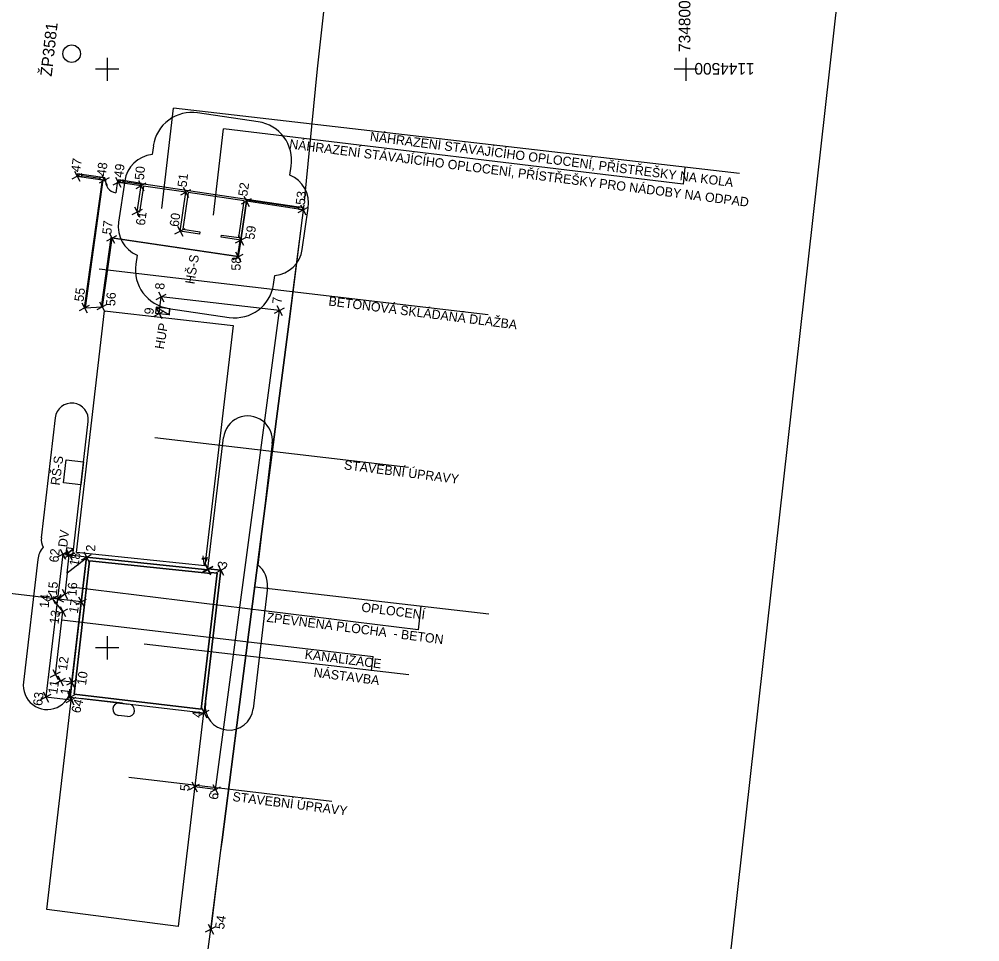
# Model space of a CAD drawing. Extents: x -734953 to -734775, y -1144697 to -1144368.
# Drawn here: x -734857.6 to -734774.6, y -1144575.4 to -1144495.7 of the extents above; entities that cross this region are included whole.
import ezdxf

# ---------------------------------------------------------------- set-up
doc = ezdxf.new("R2010")
doc.units = 0
for name, color, linetype in [('000_rozpiska', 7, 'Continuous'), ('A3_Netisk', 7, 'Continuous'), ('A3_SIT_OBJEKTY_N01', 7, 'Continuous'), ('A3_SIT_OBJEKTY_S01', 7, 'Continuous'), ('A3_SIT_PNB', 7, 'Continuous'), ('CKKOTY', 7, 'Continuous'), ('CKPLYN_POTRUBI_NT_PODZ_N', 7, 'Continuous'), ('CKTEXTY_MALE', 7, 'Continuous'), ('Katastr_HRANICE DRÁHY', 7, 'Continuous'), ('PROGI_rozpiska', 7, 'Continuous'), ('PROGI_vytyč_body', 7, 'Continuous'), ('PROGI_vytyč_čísla', 7, 'Continuous'), ('SO01_CKKANALIZACE_JEDNOTNA_PODZ_N', 7, 'Continuous'), ('čtvercová síť', 7, 'Continuous')]:
    doc.layers.add(name, color=color, linetype=linetype)

# ---------------------------------------------------------------- blocks, each defined once
blk = doc.blocks.new('POINT_DISPLAY')
for p, q in [((-0.35, -0.35), (0.35, 0.35)), ((-0.35, 0.35), (0.35, -0.35))]:
    blk.add_line(p, q)

msp = doc.modelspace()

# ---------------------------------------------------------------- linework, layer by layer
for p, q in [((-734795.363, -1144509.022), (-734844.273, -1144503.372)), ((-734817.078, -1144521.235), (-734850.682, -1144517.28)), ((-734823.968, -1144534.411), (-734845.892, -1144531.85)), ((-734853.579, -1144541.96), (-734852.914, -1144541.433)), ((-734817.019, -1144547.087), (-734837.249, -1144544.759)), ((-734823.952, -1144552.341), (-734846.794, -1144549.683)), ((-734830.58, -1144563.282), (-734848.143, -1144561.209))]:
    msp.add_line(p, q)
for points in [[(-734853.579, -1144541.96), (-734852.983, -1144542.029), (-734852.914, -1144541.433), (-734853.51, -1144541.364)], [(-734853.579, -1144541.96), (-734852.983, -1144542.029), (-734852.914, -1144541.433)]]:
    msp.add_lwpolyline(points, close=True)
at = {"layer": '000_rozpiska'}
msp.add_line((-734809.638, -1144697.109), (-734774.606, -1144384.063), dxfattribs=at)
at = {"layer": 'A3_Netisk'}
for p, q in [((-734800.085, -1144508.477), (-734800.248, -1144509.94)), ((-734838.465, -1144514.774), (-734837.936, -1144511.213)), ((-734851.783, -1144542.154), (-734853.2, -1144554.266)), ((-734848.694, -1144554.798), (-734852.306, -1144554.375))]:
    msp.add_line(p, q, dxfattribs=at)
msp.add_lwpolyline([(-734852.04, -1144533.939), (-734852.27, -1144535.925), (-734853.791, -1144535.749), (-734853.561, -1144533.763)], close=True, dxfattribs=at)
at = {"layer": 'A3_SIT_OBJEKTY_N01'}
for p, q in [((-734851.963, -1144520.613), (-734850.421, -1144509.56)), ((-734850.371, -1144509.567), (-734851.914, -1144520.619)), ((-734850.626, -1144509.529), (-734850.597, -1144509.332)), ((-734850.23, -1144509.588), (-734850.626, -1144509.529)), ((-734850.597, -1144509.332), (-734850.201, -1144509.39)), ((-734850.421, -1144509.56), (-734850.371, -1144509.567)), ((-734850.201, -1144509.39), (-734850.23, -1144509.588)), ((-734849.043, -1144509.765), (-734849.014, -1144509.567)), ((-734848.648, -1144509.823), (-734849.043, -1144509.765)), ((-734849.014, -1144509.567), (-734848.618, -1144509.626)), ((-734848.618, -1144509.626), (-734848.648, -1144509.823)), ((-734847.403, -1144512.334), (-734847.036, -1144509.861)), ((-734847.036, -1144509.861), (-734837.936, -1144511.213)), ((-734846.867, -1144510.088), (-734847.205, -1144512.363)), ((-734843.207, -1144510.632), (-734846.867, -1144510.088)), ((-734843.707, -1144513.995), (-734843.207, -1144510.632)), ((-734843.01, -1144510.661), (-734843.48, -1144513.826)), ((-734838.163, -1144511.381), (-734843.01, -1144510.661)), ((-734838.633, -1144514.546), (-734838.163, -1144511.381)), ((-734837.936, -1144511.213), (-734838.465, -1144514.774)), ((-734847.205, -1144512.363), (-734847.403, -1144512.334)), ((-734842.026, -1144514.245), (-734843.707, -1144513.995)), ((-734843.48, -1144513.826), (-734841.996, -1144514.047)), ((-734841.996, -1144514.047), (-734842.026, -1144514.245)), ((-734850.488, -1144520.532), (-734849.65, -1144514.527)), ((-734849.607, -1144514.584), (-734850.438, -1144520.538)), ((-734849.65, -1144514.527), (-734838.72, -1144516.151)), ((-734838.678, -1144516.208), (-734849.607, -1144514.584)), ((-734840.146, -1144514.524), (-734840.117, -1144514.326)), ((-734838.465, -1144514.774), (-734840.146, -1144514.524)), ((-734840.117, -1144514.326), (-734838.633, -1144514.546)), ((-734838.72, -1144516.151), (-734838.514, -1144514.766)), ((-734838.465, -1144514.774), (-734838.678, -1144516.208)), ((-734838.514, -1144514.766), (-734838.465, -1144514.774)), ((-734851.914, -1144520.619), (-734851.963, -1144520.613)), ((-734851.914, -1144520.619), (-734850.438, -1144520.538)), ((-734850.438, -1144520.538), (-734850.488, -1144520.532)), ((-734853.848, -1144541.911), (-734855.291, -1144554.247)), ((-734851.783, -1144542.154), (-734853.848, -1144541.911)), ((-734851.783, -1144542.154), (-734853.2, -1144554.27)), ((-734853.2, -1144554.27), (-734851.783, -1144542.154)), ((-734841.306, -1144543.249), (-734851.783, -1144542.154)), ((-734852.868, -1144554.007), (-734851.519, -1144542.484)), ((-734851.519, -1144542.484), (-734841.043, -1144543.578)), ((-734841.297, -1144543.168), (-734841.306, -1144543.249)), ((-734840.177, -1144543.299), (-734841.297, -1144543.168)), ((-734840.51, -1144543.563), (-734841.883, -1144555.293)), ((-734841.619, -1144555.625), (-734840.177, -1144543.299)), ((-734841.043, -1144543.578), (-734841.034, -1144543.501)), ((-734841.034, -1144543.501), (-734840.51, -1144543.563)), ((-734841.883, -1144555.293), (-734852.868, -1144554.007)), ((-734855.291, -1144554.247), (-734853.107, -1144554.503)), ((-734853.2, -1144554.27), (-734841.619, -1144555.625)), ((-734853.081, -1144554.284), (-734853.2, -1144554.27)), ((-734853.107, -1144554.503), (-734853.081, -1144554.284))]:
    msp.add_line(p, q, dxfattribs=at)
for points in [[(-734852.604, -1144509.236), (-734852.209, -1144509.294), (-734852.179, -1144509.097), (-734852.575, -1144509.038)], [(-734852.604, -1144509.236), (-734850.23, -1144509.588), (-734850.201, -1144509.39), (-734852.575, -1144509.038)], [(-734851.914, -1144520.619), (-734851.963, -1144520.613), (-734850.421, -1144509.56), (-734850.371, -1144509.567)], [(-734850.626, -1144509.529), (-734850.23, -1144509.588), (-734850.201, -1144509.39), (-734850.201, -1144509.39), (-734850.597, -1144509.332)], [(-734849.014, -1144509.567), (-734849.043, -1144509.765), (-734848.648, -1144509.823), (-734848.618, -1144509.626)], [(-734847.036, -1144509.861), (-734848.618, -1144509.626), (-734848.648, -1144509.823), (-734847.065, -1144510.059)], [(-734842.026, -1144514.245), (-734843.707, -1144513.995), (-734843.207, -1144510.632), (-734846.867, -1144510.088), (-734847.205, -1144512.363), (-734847.403, -1144512.334), (-734847.036, -1144509.861), (-734837.936, -1144511.213), (-734838.465, -1144514.774), (-734840.146, -1144514.524), (-734840.117, -1144514.326), (-734838.633, -1144514.546), (-734838.163, -1144511.381), (-734843.01, -1144510.661), (-734843.48, -1144513.826), (-734841.996, -1144514.047)], [(-734833.464, -1144512.079), (-734837.965, -1144511.411), (-734837.936, -1144511.213), (-734833.435, -1144511.881)], [(-734833.464, -1144512.079), (-734833.069, -1144512.138), (-734833.039, -1144511.94), (-734833.435, -1144511.881)], [(-734838.465, -1144514.774), (-734838.678, -1144516.208), (-734849.607, -1144514.584), (-734850.438, -1144520.538), (-734850.488, -1144520.532), (-734849.65, -1144514.527), (-734838.72, -1144516.151), (-734838.514, -1144514.766)], [(-734841.297, -1144543.168), (-734841.306, -1144543.249), (-734851.783, -1144542.154), (-734853.2, -1144554.27), (-734841.619, -1144555.625), (-734840.177, -1144543.299)], [(-734841.034, -1144543.501), (-734841.043, -1144543.578), (-734851.519, -1144542.484), (-734852.868, -1144554.007), (-734841.883, -1144555.293), (-734840.51, -1144543.563)]]:
    msp.add_lwpolyline(points, close=True, dxfattribs=at)
for points in [[(-734852.179, -1144509.097), (-734852.209, -1144509.294), (-734852.604, -1144509.236), (-734852.575, -1144509.038), (-734852.179, -1144509.097)], [(-734850.611, -1144509.431), (-734852.194, -1144509.195)], [(-734850.136, -1144509.501), (-734850.216, -1144509.489)], [(-734849.029, -1144509.666), (-734849.108, -1144509.654), (-734849.261, -1144510.683)], [(-734847.05, -1144509.96), (-734848.633, -1144509.724)], [(-734833.45, -1144511.98), (-734837.95, -1144511.312)], [(-734833.069, -1144512.138), (-734834.23, -1144521.36), (-734836.63, -1144539.96), (-734838.79, -1144556.7), (-734840.06, -1144566.59), (-734840.228, -1144567.714), (-734841.06, -1144574.32)], [(-734833.039, -1144511.94), (-734833.069, -1144512.138), (-734833.464, -1144512.079), (-734833.435, -1144511.881), (-734833.039, -1144511.94)]]:
    msp.add_lwpolyline(points, dxfattribs=at)
msp.add_arc((-734849.108, -1144509.654), 1.04, 171.54994, 261.54908, dxfattribs=at)
at = {"layer": 'A3_SIT_OBJEKTY_S01'}
for points in [[(-734841.569, -1144542.92), (-734852.65, -1144541.762), (-734850.225, -1144520.864), (-734839.105, -1144522.145)], [(-734843.875, -1144574.096), (-734855.226, -1144572.609), (-734853.081, -1144554.284), (-734853.2, -1144554.27), (-734851.783, -1144542.154), (-734841.306, -1144543.249), (-734841.297, -1144543.168), (-734840.177, -1144543.299), (-734841.619, -1144555.625), (-734841.686, -1144555.618)]]:
    msp.add_lwpolyline(points, close=True, dxfattribs=at)
at = {"layer": 'A3_SIT_PNB'}
for points in [[(-734836.945, -1144504.546), (-734842.187, -1144503.767)], [(-734846.016, -1144506.605), (-734846.13, -1144507.371)], [(-734834.221, -1144509.14), (-734834.107, -1144508.375)], [(-734848.49, -1144509.645), (-734849.019, -1144513.206)], [(-734833.153, -1144515.563), (-734832.624, -1144512.002)], [(-734847.422, -1144516.067), (-734847.536, -1144516.833)], [(-734835.626, -1144518.602), (-734835.513, -1144517.837)], [(-734844.698, -1144520.662), (-734839.455, -1144521.44)], [(-734854.49, -1144530.117), (-734855.694, -1144540.487)], [(-734851.783, -1144542.154), (-734852.983, -1144542.029), (-734851.639, -1144530.45)], [(-734841.297, -1144543.168), (-734839.952, -1144531.834)], [(-734835.742, -1144532.333), (-734836.991, -1144542.861)], [(-734855.997, -1144542.375), (-734857.235, -1144552.957)], [(-734853.103, -1144553.441), (-734851.783, -1144542.154)], [(-734841.522, -1144554.796), (-734840.177, -1144543.299), (-734841.297, -1144543.168), (-734841.297, -1144543.168)], [(-734836.162, -1144544.775), (-734837.391, -1144555.279)], [(-734848.915, -1144554.772), (-734848.12, -1144554.865)], [(-734848.246, -1144555.937), (-734849.04, -1144555.844)]]:
    msp.add_lwpolyline(points, dxfattribs=at)
for centre, radius, start, end in [((-734842.683, -1144507.1), 3.37, 81.54908, 171.54908), ((-734837.44, -1144507.879), 3.37, 351.54908, 81.54908), ((-734845.834, -1144510.039), 2.685, 96.32984, 171.54908), ((-734835.28, -1144511.607), 2.685, 351.54908, 66.76833), ((-734846.363, -1144513.6), 2.685, 171.54908, 246.76833), ((-734835.809, -1144515.168), 2.685, 276.32984, 351.54908), ((-734844.202, -1144517.328), 3.37, 171.54908, 261.54908), ((-734838.96, -1144518.107), 3.37, 261.54908, 351.54908), ((-734853.064, -1144530.283), 1.435, 353.33341, 173.32709), ((-734837.847, -1144532.083), 2.12, 353.23643, 173.23644), ((-734854.268, -1144540.654), 1.435, 173.32808, 207.03421), ((-734853.931, -1144542.616), 2.08, 140.96329, 173.32599), ((-734838.227, -1144544.534), 2.08, 353.32599, 53.51095), ((-734855.176, -1144553.254), 2.081, 171.79921, 354.85276), ((-734848.977, -1144555.308), 0.54, 83.32837, 263.32599), ((-734848.977, -1144555.303), 0.535, 83.32351, 83.32831), ((-734839.457, -1144555.038), 2.08, 173.32599, 353.32599), ((-734848.183, -1144555.401), 0.54, 263.32927, 83.32599)]:
    msp.add_arc(centre, radius, start, end, dxfattribs=at)
at = {"layer": 'CKKOTY'}
for p in [(-734840.821, -1144512.604), (-734800.248, -1144509.94)]:
    msp.add_line(p, (-734839.948, -1144505.137), dxfattribs=at)
at = {"layer": 'CKPLYN_POTRUBI_NT_PODZ_N'}
for p, q in [((-734845.514, -1144521.105), (-734845.346, -1144519.67)), ((-734845.775, -1144520.57), (-734845.833, -1144521.066)), ((-734844.583, -1144520.71), (-734845.775, -1144520.57)), ((-734844.641, -1144521.205), (-734844.583, -1144520.71)), ((-734845.833, -1144521.066), (-734844.641, -1144521.205)), ((-734840.638, -1144562.238), (-734842.453, -1144562.022))]:
    msp.add_line(p, q, dxfattribs=at)
msp.add_lwpolyline([(-734840.638, -1144562.238), (-734835.108, -1144520.855), (-734845.346, -1144519.67)], dxfattribs=at)
msp.add_lwpolyline([(-734844.633, -1144521.222), (-734844.583, -1144520.71), (-734845.773, -1144520.571)], close=True, dxfattribs=at)
at = {"layer": 'CKTEXTY_MALE'}
for p, q in [((-734845.287, -1144512.041), (-734844.273, -1144503.372)), ((-734823.141, -1144548.436), (-734853.076, -1144544.769)), ((-734822.904, -1144546.41), (-734823.141, -1144548.436)), ((-734853.929, -1144547.589), (-734827.014, -1144550.739)), ((-734827.159, -1144551.98), (-734827.014, -1144550.739))]:
    msp.add_line(p, q, dxfattribs=at)
at = {"layer": 'Katastr_HRANICE DRÁHY'}
for points in [[(-734831.84, -1144499.97), (-734830.54, -1144488.25)], [(-734832.95, -1144511.4), (-734831.84, -1144499.97)], [(-734833.069, -1144512.138), (-734834.23, -1144521.36), (-734836.63, -1144539.96), (-734838.79, -1144556.7), (-734840.06, -1144566.59), (-734840.228, -1144567.714), (-734841.06, -1144574.32)], [(-734834.23, -1144521.36), (-734832.99, -1144511.73)], [(-734836.63, -1144539.96), (-734834.23, -1144521.36)], [(-734838.79, -1144556.7), (-734836.63, -1144539.96)], [(-734840.06, -1144566.59), (-734838.79, -1144556.7)], [(-734841.06, -1144574.32), (-734840.06, -1144566.59)], [(-734841.28, -1144576.06), (-734841.06, -1144574.32)]]:
    msp.add_lwpolyline(points, dxfattribs=at)
at = {"layer": 'PROGI_rozpiska'}
msp.add_circle((-734853.076, -1144498.652), 0.756, dxfattribs=at)
at = {"layer": 'SO01_CKKANALIZACE_JEDNOTNA_PODZ_N'}
msp.add_line((-734853.457, -1144543.555), (-734853.276, -1144541.995), dxfattribs=at)
for points in [[(-734851.904, -1144542.327), (-734853.457, -1144543.555), (-734853.669, -1144545.365), (-734854.223, -1144545.804)], [(-734852.237, -1144546.036), (-734854.223, -1144545.804), (-734854.72, -1144545.746), (-734865.823, -1144544.448), (-734866.393, -1144544.885)], [(-734853.049, -1144552.979), (-734854.043, -1144552.863), (-734854.481, -1144552.308), (-734853.843, -1144546.855), (-734854.72, -1144545.746)]]:
    msp.add_lwpolyline(points, dxfattribs=at)
at = {"layer": 'čtvercová síť'}
for p, q in [((-734850, -1144499), (-734850, -1144501)), ((-734800, -1144499), (-734800, -1144501)), ((-734849, -1144500), (-734851, -1144500)), ((-734799, -1144500), (-734801, -1144500)), ((-734850, -1144549), (-734850, -1144551)), ((-734849, -1144550), (-734851, -1144550))]:
    msp.add_line(p, q, dxfattribs=at)

# ---------------------------------------------------------------- block references
at = {"layer": 'PROGI_vytyč_body'}
for p, rotation in [((-734852.604, -1144509.236), -17.15277001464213), ((-734850.23, -1144509.588), -17.15277001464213), ((-734849.043, -1144509.765), -17.15277001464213), ((-734847.065, -1144510.059), -17.15277001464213), ((-734843.207, -1144510.632), -17.15277001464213), ((-734837.965, -1144511.411), -17.15277001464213), ((-734847.403, -1144512.334), -17.15277001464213), ((-734833.069, -1144512.143), -17.15277001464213), ((-734849.607, -1144514.584), -17.15277001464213), ((-734843.707, -1144513.995), -17.15277001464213), ((-734838.465, -1144514.774), -17.15277001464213), ((-734838.678, -1144516.208), -17.15277001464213), ((-734845.346, -1144519.67), -17.15277001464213), ((-734851.963, -1144520.613), -17.15277001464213), ((-734850.438, -1144520.538), -17.15277001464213), ((-734845.514, -1144521.103), -17.15277001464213), ((-734835.108, -1144520.855), -17.15277001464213), ((-734853.848, -1144541.911), -17.15277001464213), ((-734853.274, -1144541.981), -17.15277001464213), ((-734851.783, -1144542.154), -17.15277001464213), ((-734841.306, -1144543.247), -17.15277001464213), ((-734841.297, -1144543.168), -17.15277001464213), ((-734840.177, -1144543.299), -17.15277001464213), ((-734854.72, -1144545.746), -17.15277001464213), ((-734854.223, -1144545.804), 17.15277001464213), ((-734853.669, -1144545.365), -17.15277001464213), ((-734852.237, -1144546.036), -17.15277001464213), ((-734853.843, -1144546.855), -17.15277001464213), ((-734854.481, -1144552.308), -17.15277001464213), ((-734854.043, -1144552.863), -17.15277001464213), ((-734853.049, -1144552.979), -17.15277001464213), ((-734855.291, -1144554.247), -17.15277001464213), ((-734853.2, -1144554.27), -17.15277001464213), ((-734853.107, -1144554.503), -17.15277001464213), ((-734841.619, -1144555.625), -17.15277001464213), ((-734842.453, -1144562.022), -17.15277001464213), ((-734840.638, -1144562.238), -17.15277001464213), ((-734841.06, -1144574.32), -17.15277001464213)]:
    msp.add_blockref('POINT_DISPLAY', p, dxfattribs=dict(at, rotation=rotation))

# ---------------------------------------------------------------- texts
at = {"layer": 'PROGI_rozpiska'}
for s, height, rotation, p in [('ŽP3581', 1, 83.53066, (-734854.8, -1144500.656)), ('NÁHRAZENÍ STÁVAJÍCÍHO OPLOCENÍ, PŘÍSTŘEŠKY NA KOLA', 0.8, 352.74798, (-734827.334, -1144506.185)), ('NÁHRAZENÍ STÁVAJÍCÍHO OPLOCENÍ, PŘÍSTŘEŠKY PRO NÁDOBY NA ODPAD', 0.8, 352.74798, (-734834.302, -1144506.836)), ('HŠ-S', 0.8, 80.62415, (-734842.478, -1144518.61)), ('BETONOVÁ SKLÁDANÁ DLAŽBA', 0.8, 352.74798, (-734830.914, -1144520.409)), ('HUP', 0.8, 80.62415, (-734845.107, -1144524.234)), ('RŠ-S', 0.8, 82.84405, (-734854.107, -1144535.998)), ('STAVEBNÍ ÚPRAVY', 0.8, 352.74798, (-734829.572, -1144534.569)), ('DV', 0.8, 82.84405, (-734853.461, -1144541.342)), ('OPLOCENÍ', 0.8, 352.74798, (-734828.076, -1144546.866)), ('ZPEVNĚNÁ PLOCHA  - BETON', 0.8, 352.74798, (-734836.272, -1144547.745)), ('KANALIZACE', 0.8, 352.74798, (-734832.967, -1144550.947)), ('NÁSTAVBA', 0.8, 352.74798, (-734832.198, -1144552.499)), ('STAVEBNÍ ÚPRAVY', 0.8, 352.74798, (-734839.208, -1144563.237))]:
    msp.add_text(s, height=height, rotation=rotation, dxfattribs=at).set_placement(p)
at = {"layer": 'PROGI_vytyč_čísla'}
for s, rotation, p in [('47', 81.91141, (-734852.348, -1144508.927)), ('48', 82.84716, (-734850.122, -1144509.274)), ('49', 81.78232, (-734848.651, -1144509.405)), ('50', 84.47402, (-734846.837, -1144509.6)), ('51', 83.67742, (-734843.142, -1144510.229)), ('52', 81.92732, (-734837.903, -1144511.023)), ('53', 83.59955, (-734832.928, -1144511.762)), ('61', 82.1138, (-734846.751, -1144513.542)), ('60', 82.05497, (-734843.832, -1144513.655)), ('57', 83.75246, (-734849.647, -1144514.309)), ('59', 82.1589, (-734837.293, -1144514.752)), ('58', 88.49654, (-734838.48, -1144517.409)), ('55', 82.62415, (-734852.057, -1144520.115)), ('8', 84.9486, (-734845.078, -1144519.075)), ('56', 87.06097, (-734849.31, -1144520.48)), ('7', 88.04772, (-734834.93, -1144520.269)), ('9', 84.77282, (-734846.006, -1144521.222)), ('62', 84.00861, (-734854.22, -1144542.653)), ('2', 87.6067, (-734851.048, -1144541.701)), ('18', 78.87342, (-734852.509, -1144542.999)), ('4', 188.19624, (-734841.326, -1144542.052)), ('4', 188.19624, (-734841.316, -1144541.973)), ('3', 80.9798, (-734839.694, -1144543.171)), ('15', 84.60287, (-734854.358, -1144545.499)), ('16', 86.46326, (-734852.659, -1144545.555)), ('14', 85.50392, (-734855.057, -1144546.583)), ('17', 80.02078, (-734852.551, -1144547.065)), ('13', 81.46667, (-734854.218, -1144547.988)), ('12', 81.81988, (-734853.487, -1144551.993)), ('10', 81.72762, (-734851.841, -1144553.277)), ('11', 81.30524, (-734854.328, -1144554.043)), ('63', 82.5529, (-734855.634, -1144555.056)), ('1', 83.25334, (-734853.267, -1144554.097)), ('64', 75.47842, (-734852.35, -1144555.707)), ('4', 87.47899, (-734841.86, -1144556.061)), ('5', 83.68375, (-734842.93, -1144562.43)), ('6', 79.75153, (-734840.464, -1144563.175)), ('54', 80.93621, (-734839.913, -1144574.372))]:
    msp.add_text(s, height=0.8, rotation=rotation, dxfattribs=at).set_placement(p)
at = {"layer": 'čtvercová síť'}
for s, rotation, p in [('734800', 90, (-734799.612, -1144498.504)), ('1144500', 179.81101, (-734794.06, -1144499.469))]:
    msp.add_text(s, height=1, rotation=rotation, dxfattribs=at).set_placement(p)

doc.saveas('drawing.dxf')
